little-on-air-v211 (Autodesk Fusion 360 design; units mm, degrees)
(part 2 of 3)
sketch "MODE terminal row clearance profile" plane through (0, 0, -13.9) normal (0, 0, 1) x axis (1, 0, 0)
  line L1 (63.1, 53.64) -> (56.9, 53.64)
  line L2 (63.1, 55.29) -> (63.1, 53.64)
  line L3 (56.9, 55.29) -> (63.1, 55.29)
  line L4 (56.9, 53.64) -> (56.9, 55.29)
  point P2 (56.9, 53.64)
  point P3 (63.1, 53.64)
  point P4 (63.1, 55.29)
  dimension "d508" distance P2 P3 = 6.2
  dimension "d509" distance P3 P4 = 1.65
extrude "Extrude67" cut sketch "MODE terminal row clearance profile" against normal blind 1.1
work_plane "WorkPlane68" AlongDistance -16.92 ExtraOffset 0
sketch "MODE terminal row clearance profile (1)" plane through (0, 0, -16.92) normal (0, 0, 1) x axis (1, 0, 0)
  line L1 (63.1, 53.64) -> (56.9, 53.64)
  line L2 (63.1, 55.29) -> (63.1, 53.64)
  line L3 (56.9, 55.29) -> (63.1, 55.29)
  line L4 (56.9, 53.64) -> (56.9, 55.29)
  point P2 (56.9, 53.64)
  point P3 (63.1, 53.64)
  point P4 (63.1, 55.29)
  dimension "d514" distance P2 P3 = 6.2
  dimension "d515" distance P3 P4 = 1.65
extrude "Extrude68" cut sketch "MODE terminal row clearance profile (1)" against normal blind 1.1
work_plane "WorkPlane69" AlongDistance -9.48 ExtraOffset 0
sketch "MODE direct actuator top aperture profile" plane through (0, 0, -9.48) normal (0, 0, 1) x axis (1, 0, 0)
  line L1 (62.2, 58.85) -> (57.8, 58.85)
  line L2 (62.2, 60.15) -> (62.2, 58.85)
  line L3 (57.8, 60.15) -> (62.2, 60.15)
  line L4 (57.8, 58.85) -> (57.8, 60.15)
  point P2 (57.8, 58.85)
  point P3 (62.2, 58.85)
  point P4 (62.2, 60.15)
  dimension "d520" distance P2 P3 = 4.4
  dimension "d521" distance P3 P4 = 1.3
extrude "Extrude69" cut sketch "MODE direct actuator top aperture profile" against normal blind 7.53
work_plane "WorkPlane70" AlongDistance -9.48 ExtraOffset 0
sketch "Side tongue clearance profile" plane through (0, 0, -9.48) normal (0, 0, 1) x axis (1, 0, 0)
  line L1 (4.1, 16.75) -> (2.4, 16.75)
  line L2 (4.1, 26.25) -> (4.1, 16.75)
  line L3 (2.4, 26.25) -> (4.1, 26.25)
  line L4 (2.4, 16.75) -> (2.4, 26.25)
  point P2 (2.4, 16.75)
  point P3 (4.1, 16.75)
  point P4 (4.1, 26.25)
  dimension "d526" distance P2 P3 = 1.7
  dimension "d527" distance P3 P4 = 9.5
work_plane "WorkPlane71" AlongDistance -9.48 ExtraOffset 0
sketch "Side tongue clearance profile (1)" plane through (0, 0, -9.48) normal (0, 0, 1) x axis (1, 0, 0)
  line L1 (117.6, 16.75) -> (115.9, 16.75)
  line L2 (117.6, 26.25) -> (117.6, 16.75)
  line L3 (115.9, 26.25) -> (117.6, 26.25)
  line L4 (115.9, 16.75) -> (115.9, 26.25)
  point P2 (115.9, 16.75)
  point P3 (117.6, 16.75)
  point P4 (117.6, 26.25)
  dimension "d532" distance P2 P3 = 1.7
  dimension "d533" distance P3 P4 = 9.5
work_plane "WorkPlane72" AlongDistance -9.48 ExtraOffset 0
sketch "Top tongue clearance profile" plane through (0, 0, -9.48) normal (0, 0, 1) x axis (1, 0, 0)
  line L1 (46.25, 55.9) -> (35.75, 55.9)
  line L2 (46.25, 57.6) -> (46.25, 55.9)
  line L3 (35.75, 57.6) -> (46.25, 57.6)
  line L4 (35.75, 55.9) -> (35.75, 57.6)
  point P2 (35.75, 55.9)
  point P3 (46.25, 55.9)
  point P4 (46.25, 57.6)
  dimension "d538" distance P2 P3 = 10.5
  dimension "d539" distance P3 P4 = 1.7
work_plane "WorkPlane73" AlongDistance -16.5 ExtraOffset 0
sketch "Charger rear LED viewing hole profile" plane through (0, 0, -16.5) normal (0, 0, 1) x axis (1, 0, 0)
  circle C1 centre (14, 49.4) radius 1.6
  dimension "d544" diameter C1 = 3.2
extrude "Extrude73" cut sketch "Charger rear LED viewing hole profile" against normal blind 7.7
work_plane "WorkPlane74" AlongDistance -16.5 ExtraOffset 0
sketch "Charger rear LED viewing hole profile (1)" plane through (0, 0, -16.5) normal (0, 0, 1) x axis (1, 0, 0)
  circle C1 centre (14, 44.65) radius 1.6
  dimension "d549" diameter C1 = 3.2
extrude "Extrude74" cut sketch "Charger rear LED viewing hole profile (1)" against normal blind 7.7
work_plane "WorkPlane75" AlongDistance -0.1 ExtraOffset 0
sketch "Angled pill vent" plane through (-0.1, 0, 0) normal (1, 0, 0) x axis (0, 0, -1)
  line L1 (17.3263, 17.9863) -> (17.1314, 17.8284)
  line L2 (17.5499, 18.1002) -> (17.3263, 17.9863)
  line L3 (17.7922, 18.1651) -> (17.5499, 18.1002)
  line L4 (18.0427, 18.1783) -> (17.7922, 18.1651)
  line L5 (18.2905, 18.139) -> (18.0427, 18.1783)
  line L6 (18.5247, 18.0491) -> (18.2905, 18.139)
  line L7 (18.7351, 17.9125) -> (18.5247, 18.0491)
  line L8 (18.9125, 17.7351) -> (18.7351, 17.9125)
  line L9 (19.0491, 17.5247) -> (18.9125, 17.7351)
  line L10 (19.139, 17.2905) -> (19.0491, 17.5247)
  line L11 (19.1783, 17.0427) -> (19.139, 17.2905)
  line L12 (19.1651, 16.7922) -> (19.1783, 17.0427)
  line L13 (19.1002, 16.5499) -> (19.1651, 16.7922)
  line L14 (18.9863, 16.3263) -> (19.1002, 16.5499)
  line L15 (18.8284, 16.1314) -> (18.9863, 16.3263)
  line L16 (14.8686, 12.1716) -> (18.8284, 16.1314)
  line L17 (14.6737, 12.0137) -> (14.8686, 12.1716)
  line L18 (14.4501, 11.8998) -> (14.6737, 12.0137)
  line L19 (14.2078, 11.8349) -> (14.4501, 11.8998)
  line L20 (13.9573, 11.8217) -> (14.2078, 11.8349)
  line L21 (13.7095, 11.861) -> (13.9573, 11.8217)
  line L22 (13.4753, 11.9509) -> (13.7095, 11.861)
  line L23 (13.2649, 12.0875) -> (13.4753, 11.9509)
  line L24 (13.0875, 12.2649) -> (13.2649, 12.0875)
  line L25 (12.9509, 12.4753) -> (13.0875, 12.2649)
  line L26 (12.861, 12.7095) -> (12.9509, 12.4753)
  line L27 (12.8217, 12.9573) -> (12.861, 12.7095)
  line L28 (12.8349, 13.2078) -> (12.8217, 12.9573)
  line L29 (12.8998, 13.4501) -> (12.8349, 13.2078)
  line L30 (13.0137, 13.6737) -> (12.8998, 13.4501)
  line L31 (13.1716, 13.8686) -> (13.0137, 13.6737)
  line L32 (17.1314, 17.8284) -> (13.1716, 13.8686)
extrude "Extrude75" cut sketch "Angled pill vent" along normal blind 2.65
work_plane "WorkPlane76" AlongDistance -0.1 ExtraOffset 0
sketch "Angled pill vent (1)" plane through (-0.1, 0, 0) normal (1, 0, 0) x axis (0, 0, -1)
  line L1 (17.3263, 26.9863) -> (17.1314, 26.8284)
  line L2 (17.5499, 27.1002) -> (17.3263, 26.9863)
  line L3 (17.7922, 27.1651) -> (17.5499, 27.1002)
  line L4 (18.0427, 27.1783) -> (17.7922, 27.1651)
  line L5 (18.2905, 27.139) -> (18.0427, 27.1783)
  line L6 (18.5247, 27.0491) -> (18.2905, 27.139)
  line L7 (18.7351, 26.9125) -> (18.5247, 27.0491)
  line L8 (18.9125, 26.7351) -> (18.7351, 26.9125)
  line L9 (19.0491, 26.5247) -> (18.9125, 26.7351)
  line L10 (19.139, 26.2905) -> (19.0491, 26.5247)
  line L11 (19.1783, 26.0427) -> (19.139, 26.2905)
  line L12 (19.1651, 25.7922) -> (19.1783, 26.0427)
  line L13 (19.1002, 25.5499) -> (19.1651, 25.7922)
  line L14 (18.9863, 25.3263) -> (19.1002, 25.5499)
  line L15 (18.8284, 25.1314) -> (18.9863, 25.3263)
  line L16 (14.8686, 21.1716) -> (18.8284, 25.1314)
  line L17 (14.6737, 21.0137) -> (14.8686, 21.1716)
  line L18 (14.4501, 20.8998) -> (14.6737, 21.0137)
  line L19 (14.2078, 20.8349) -> (14.4501, 20.8998)
  line L20 (13.9573, 20.8217) -> (14.2078, 20.8349)
  line L21 (13.7095, 20.861) -> (13.9573, 20.8217)
  line L22 (13.4753, 20.9509) -> (13.7095, 20.861)
  line L23 (13.2649, 21.0875) -> (13.4753, 20.9509)
  line L24 (13.0875, 21.2649) -> (13.2649, 21.0875)
  line L25 (12.9509, 21.4753) -> (13.0875, 21.2649)
  line L26 (12.861, 21.7095) -> (12.9509, 21.4753)
  line L27 (12.8217, 21.9573) -> (12.861, 21.7095)
  line L28 (12.8349, 22.2078) -> (12.8217, 21.9573)
  line L29 (12.8998, 22.4501) -> (12.8349, 22.2078)
  line L30 (13.0137, 22.6737) -> (12.8998, 22.4501)
  line L31 (13.1716, 22.8686) -> (13.0137, 22.6737)
  line L32 (17.1314, 26.8284) -> (13.1716, 22.8686)
extrude "Extrude76" cut sketch "Angled pill vent (1)" along normal blind 2.65
work_plane "WorkPlane77" AlongDistance -0.1 ExtraOffset 0
sketch "Angled pill vent (2)" plane through (-0.1, 0, 0) normal (1, 0, 0) x axis (0, 0, -1)
  line L1 (17.3263, 35.9863) -> (17.1314, 35.8284)
  line L2 (17.5499, 36.1002) -> (17.3263, 35.9863)
  line L3 (17.7922, 36.1651) -> (17.5499, 36.1002)
  line L4 (18.0427, 36.1783) -> (17.7922, 36.1651)
  line L5 (18.2905, 36.139) -> (18.0427, 36.1783)
  line L6 (18.5247, 36.0491) -> (18.2905, 36.139)
  line L7 (18.7351, 35.9125) -> (18.5247, 36.0491)
  line L8 (18.9125, 35.7351) -> (18.7351, 35.9125)
  line L9 (19.0491, 35.5247) -> (18.9125, 35.7351)
  line L10 (19.139, 35.2905) -> (19.0491, 35.5247)
  line L11 (19.1783, 35.0427) -> (19.139, 35.2905)
  line L12 (19.1651, 34.7922) -> (19.1783, 35.0427)
  line L13 (19.1002, 34.5499) -> (19.1651, 34.7922)
  line L14 (18.9863, 34.3263) -> (19.1002, 34.5499)
  line L15 (18.8284, 34.1314) -> (18.9863, 34.3263)
  line L16 (14.8686, 30.1716) -> (18.8284, 34.1314)
  line L17 (14.6737, 30.0137) -> (14.8686, 30.1716)
  line L18 (14.4501, 29.8998) -> (14.6737, 30.0137)
  line L19 (14.2078, 29.8349) -> (14.4501, 29.8998)
  line L20 (13.9573, 29.8217) -> (14.2078, 29.8349)
  line L21 (13.7095, 29.861) -> (13.9573, 29.8217)
  line L22 (13.4753, 29.9509) -> (13.7095, 29.861)
  line L23 (13.2649, 30.0875) -> (13.4753, 29.9509)
  line L24 (13.0875, 30.2649) -> (13.2649, 30.0875)
  line L25 (12.9509, 30.4753) -> (13.0875, 30.2649)
  line L26 (12.861, 30.7095) -> (12.9509, 30.4753)
  line L27 (12.8217, 30.9573) -> (12.861, 30.7095)
  line L28 (12.8349, 31.2078) -> (12.8217, 30.9573)
  line L29 (12.8998, 31.4501) -> (12.8349, 31.2078)
  line L30 (13.0137, 31.6737) -> (12.8998, 31.4501)
  line L31 (13.1716, 31.8686) -> (13.0137, 31.6737)
  line L32 (17.1314, 35.8284) -> (13.1716, 31.8686)
extrude "Extrude77" cut sketch "Angled pill vent (2)" along normal blind 2.65
work_plane "WorkPlane78" AlongDistance 117.5 ExtraOffset 0
sketch "Angled pill vent (3)" plane through (117.5, 0, 0) normal (1, 0, 0) x axis (0, 0, -1)
  line L1 (17.3263, 17.9863) -> (17.1314, 17.8284)
  line L2 (17.5499, 18.1002) -> (17.3263, 17.9863)
  line L3 (17.7922, 18.1651) -> (17.5499, 18.1002)
  line L4 (18.0427, 18.1783) -> (17.7922, 18.1651)
  line L5 (18.2905, 18.139) -> (18.0427, 18.1783)
  line L6 (18.5247, 18.0491) -> (18.2905, 18.139)
  line L7 (18.7351, 17.9125) -> (18.5247, 18.0491)
  line L8 (18.9125, 17.7351) -> (18.7351, 17.9125)
  line L9 (19.0491, 17.5247) -> (18.9125, 17.7351)
  line L10 (19.139, 17.2905) -> (19.0491, 17.5247)
  line L11 (19.1783, 17.0427) -> (19.139, 17.2905)
  line L12 (19.1651, 16.7922) -> (19.1783, 17.0427)
  line L13 (19.1002, 16.5499) -> (19.1651, 16.7922)
  line L14 (18.9863, 16.3263) -> (19.1002, 16.5499)
  line L15 (18.8284, 16.1314) -> (18.9863, 16.3263)
  line L16 (14.8686, 12.1716) -> (18.8284, 16.1314)
  line L17 (14.6737, 12.0137) -> (14.8686, 12.1716)
  line L18 (14.4501, 11.8998) -> (14.6737, 12.0137)
  line L19 (14.2078, 11.8349) -> (14.4501, 11.8998)
  line L20 (13.9573, 11.8217) -> (14.2078, 11.8349)
  line L21 (13.7095, 11.861) -> (13.9573, 11.8217)
  line L22 (13.4753, 11.9509) -> (13.7095, 11.861)
  line L23 (13.2649, 12.0875) -> (13.4753, 11.9509)
  line L24 (13.0875, 12.2649) -> (13.2649, 12.0875)
  line L25 (12.9509, 12.4753) -> (13.0875, 12.2649)
  line L26 (12.861, 12.7095) -> (12.9509, 12.4753)
  line L27 (12.8217, 12.9573) -> (12.861, 12.7095)
  line L28 (12.8349, 13.2078) -> (12.8217, 12.9573)
  line L29 (12.8998, 13.4501) -> (12.8349, 13.2078)
  line L30 (13.0137, 13.6737) -> (12.8998, 13.4501)
  line L31 (13.1716, 13.8686) -> (13.0137, 13.6737)
  line L32 (17.1314, 17.8284) -> (13.1716, 13.8686)
extrude "Extrude78" cut sketch "Angled pill vent (3)" along normal blind 2.65
work_plane "WorkPlane79" AlongDistance 117.5 ExtraOffset 0
sketch "Angled pill vent (4)" plane through (117.5, 0, 0) normal (1, 0, 0) x axis (0, 0, -1)
  line L1 (17.3263, 26.9863) -> (17.1314, 26.8284)
  line L2 (17.5499, 27.1002) -> (17.3263, 26.9863)
  line L3 (17.7922, 27.1651) -> (17.5499, 27.1002)
  line L4 (18.0427, 27.1783) -> (17.7922, 27.1651)
  line L5 (18.2905, 27.139) -> (18.0427, 27.1783)
  line L6 (18.5247, 27.0491) -> (18.2905, 27.139)
  line L7 (18.7351, 26.9125) -> (18.5247, 27.0491)
  line L8 (18.9125, 26.7351) -> (18.7351, 26.9125)
  line L9 (19.0491, 26.5247) -> (18.9125, 26.7351)
  line L10 (19.139, 26.2905) -> (19.0491, 26.5247)
  line L11 (19.1783, 26.0427) -> (19.139, 26.2905)
  line L12 (19.1651, 25.7922) -> (19.1783, 26.0427)
  line L13 (19.1002, 25.5499) -> (19.1651, 25.7922)
  line L14 (18.9863, 25.3263) -> (19.1002, 25.5499)
  line L15 (18.8284, 25.1314) -> (18.9863, 25.3263)
  line L16 (14.8686, 21.1716) -> (18.8284, 25.1314)
  line L17 (14.6737, 21.0137) -> (14.8686, 21.1716)
  line L18 (14.4501, 20.8998) -> (14.6737, 21.0137)
  line L19 (14.2078, 20.8349) -> (14.4501, 20.8998)
  line L20 (13.9573, 20.8217) -> (14.2078, 20.8349)
  line L21 (13.7095, 20.861) -> (13.9573, 20.8217)
  line L22 (13.4753, 20.9509) -> (13.7095, 20.861)
  line L23 (13.2649, 21.0875) -> (13.4753, 20.9509)
  line L24 (13.0875, 21.2649) -> (13.2649, 21.0875)
  line L25 (12.9509, 21.4753) -> (13.0875, 21.2649)
  line L26 (12.861, 21.7095) -> (12.9509, 21.4753)
  line L27 (12.8217, 21.9573) -> (12.861, 21.7095)
  line L28 (12.8349, 22.2078) -> (12.8217, 21.9573)
  line L29 (12.8998, 22.4501) -> (12.8349, 22.2078)
  line L30 (13.0137, 22.6737) -> (12.8998, 22.4501)
  line L31 (13.1716, 22.8686) -> (13.0137, 22.6737)
  line L32 (17.1314, 26.8284) -> (13.1716, 22.8686)
extrude "Extrude79" cut sketch "Angled pill vent (4)" along normal blind 2.65
work_plane "WorkPlane80" AlongDistance 117.5 ExtraOffset 0
sketch "Angled pill vent (5)" plane through (117.5, 0, 0) normal (1, 0, 0) x axis (0, 0, -1)
  line L1 (17.3263, 35.9863) -> (17.1314, 35.8284)
  line L2 (17.5499, 36.1002) -> (17.3263, 35.9863)
  line L3 (17.7922, 36.1651) -> (17.5499, 36.1002)
  line L4 (18.0427, 36.1783) -> (17.7922, 36.1651)
  line L5 (18.2905, 36.139) -> (18.0427, 36.1783)
  line L6 (18.5247, 36.0491) -> (18.2905, 36.139)
  line L7 (18.7351, 35.9125) -> (18.5247, 36.0491)
  line L8 (18.9125, 35.7351) -> (18.7351, 35.9125)
  line L9 (19.0491, 35.5247) -> (18.9125, 35.7351)
  line L10 (19.139, 35.2905) -> (19.0491, 35.5247)
  line L11 (19.1783, 35.0427) -> (19.139, 35.2905)
  line L12 (19.1651, 34.7922) -> (19.1783, 35.0427)
  line L13 (19.1002, 34.5499) -> (19.1651, 34.7922)
  line L14 (18.9863, 34.3263) -> (19.1002, 34.5499)
  line L15 (18.8284, 34.1314) -> (18.9863, 34.3263)
  line L16 (14.8686, 30.1716) -> (18.8284, 34.1314)
  line L17 (14.6737, 30.0137) -> (14.8686, 30.1716)
  line L18 (14.4501, 29.8998) -> (14.6737, 30.0137)
  line L19 (14.2078, 29.8349) -> (14.4501, 29.8998)
  line L20 (13.9573, 29.8217) -> (14.2078, 29.8349)
  line L21 (13.7095, 29.861) -> (13.9573, 29.8217)
  line L22 (13.4753, 29.9509) -> (13.7095, 29.861)
  line L23 (13.2649, 30.0875) -> (13.4753, 29.9509)
  line L24 (13.0875, 30.2649) -> (13.2649, 30.0875)
  line L25 (12.9509, 30.4753) -> (13.0875, 30.2649)
  line L26 (12.861, 30.7095) -> (12.9509, 30.4753)
  line L27 (12.8217, 30.9573) -> (12.861, 30.7095)
  line L28 (12.8349, 31.2078) -> (12.8217, 30.9573)
  line L29 (12.8998, 31.4501) -> (12.8349, 31.2078)
  line L30 (13.0137, 31.6737) -> (12.8998, 31.4501)
  line L31 (13.1716, 31.8686) -> (13.0137, 31.6737)
  line L32 (17.1314, 35.8284) -> (13.1716, 31.8686)
extrude "Extrude80" cut sketch "Angled pill vent (5)" along normal blind 2.65
work_plane "WorkPlane1" AlongDistance -9.65 ExtraOffset 0
sketch "Common 2.75 mm keeper rail profile" plane through (0, 0, -9.65) normal (0, 0, 1) x axis (1, 0, 0)
  line L1 (106.5, 34) -> (10.05, 34)
  line L2 (106.5, 38) -> (106.5, 34)
  line L3 (10.05, 38) -> (106.5, 38)
  line L4 (10.05, 34) -> (10.05, 38)
  point P2 (10.05, 34)
  point P3 (106.5, 34)
  point P4 (106.5, 38)
  dimension "d578" distance P2 P3 = 96.45
  dimension "d579" distance P3 P4 = 4
extrude "Extrude1" new body sketch "Common 2.75 mm keeper rail profile" against normal blind 2.75 bodies "Common 2.75 mm keeper rail"
work_plane "WorkPlane2" AlongDistance -9.65 ExtraOffset 0
sketch "Common screw seat profile" plane through (0, 0, -9.65) normal (0, 0, 1) x axis (1, 0, 0)
  line L1 (39.2, 33.8) -> (30.8, 33.8)
  line L2 (39.2, 42.2) -> (39.2, 33.8)
  line L3 (30.8, 42.2) -> (39.2, 42.2)
  line L4 (30.8, 33.8) -> (30.8, 42.2)
  point P2 (30.8, 33.8)
  point P3 (39.2, 33.8)
  point P4 (39.2, 42.2)
  dimension "d584" distance P2 P3 = 8.4
  dimension "d585" distance P3 P4 = 8.4
extrude "Extrude2" new body sketch "Common screw seat profile" against normal blind 2.75 bodies "Common screw seat"
work_plane "WorkPlane3" AlongDistance -9.65 ExtraOffset 0
sketch "Common screw seat profile (1)" plane through (0, 0, -9.65) normal (0, 0, 1) x axis (1, 0, 0)
  line L1 (77.2, 33.8) -> (68.8, 33.8)
  line L2 (77.2, 42.2) -> (77.2, 33.8)
  line L3 (68.8, 42.2) -> (77.2, 42.2)
  line L4 (68.8, 33.8) -> (68.8, 42.2)
  point P2 (68.8, 33.8)
  point P3 (77.2, 33.8)
  point P4 (77.2, 42.2)
  dimension "d590" distance P2 P3 = 8.4
  dimension "d591" distance P3 P4 = 8.4
extrude "Extrude3" new body sketch "Common screw seat profile (1)" against normal blind 2.75 bodies "Common screw seat (1)"
work_plane "WorkPlane4" AlongDistance -9.65 ExtraOffset 0
sketch "Charger side keeper rail profile" plane through (0, 0, -9.65) normal (0, 0, 1) x axis (1, 0, 0)
  line L1 (14.5, 33.8) -> (10.05, 33.8)
  line L2 (14.5, 57.35) -> (14.5, 33.8)
  line L3 (10.05, 57.35) -> (14.5, 57.35)
  line L4 (10.05, 33.8) -> (10.05, 57.35)
  point P2 (10.05, 33.8)
  point P3 (14.5, 33.8)
  point P4 (14.5, 57.35)
  dimension "d596" distance P2 P3 = 4.45
  dimension "d597" distance P3 P4 = 23.55
extrude "Extrude4" new body sketch "Charger side keeper rail profile" against normal blind 2.75 bodies "Charger side keeper rail"
work_plane "WorkPlane5" AlongDistance -9.65 ExtraOffset 0
sketch "Charger side keeper rail profile (1)" plane through (0, 0, -9.65) normal (0, 0, 1) x axis (1, 0, 0)
  line L1 (31.95, 33.8) -> (27.5, 33.8)
  line L2 (31.95, 57.35) -> (31.95, 33.8)
  line L3 (27.5, 57.35) -> (31.95, 57.35)
  line L4 (27.5, 33.8) -> (27.5, 57.35)
  point P2 (27.5, 33.8)
  point P3 (31.95, 33.8)
  point P4 (31.95, 57.35)
  dimension "d602" distance P2 P3 = 4.45
  dimension "d603" distance P3 P4 = 23.55
extrude "Extrude5" new body sketch "Charger side keeper rail profile (1)" against normal blind 2.75 bodies "Charger side keeper rail (1)"
work_plane "WorkPlane6" AlongDistance -12.35 ExtraOffset 0
sketch "Charger short keeper pad profile" plane through (0, 0, -12.35) normal (0, 0, 1) x axis (1, 0, 0)
  line L1 (14.65, 34.3) -> (12.25, 34.3)
  line L2 (14.65, 36.3) -> (14.65, 34.3)
  line L3 (12.25, 36.3) -> (14.65, 36.3)
  line L4 (12.25, 34.3) -> (12.25, 36.3)
  point P2 (12.25, 34.3)
  point P3 (14.65, 34.3)
  point P4 (14.65, 36.3)
  dimension "d608" distance P2 P3 = 2.4
  dimension "d609" distance P3 P4 = 2
extrude "Extrude6" new body sketch "Charger short keeper pad profile" against normal blind 2.8 bodies "Charger short keeper pad"
work_plane "WorkPlane7" AlongDistance -12.35 ExtraOffset 0
sketch "Charger short keeper pad profile (1)" plane through (0, 0, -12.35) normal (0, 0, 1) x axis (1, 0, 0)
  line L1 (14.65, 53.5) -> (12.25, 53.5)
  line L2 (14.65, 56.5) -> (14.65, 53.5)
  line L3 (12.25, 56.5) -> (14.65, 56.5)
  line L4 (12.25, 53.5) -> (12.25, 56.5)
  point P2 (12.25, 53.5)
  point P3 (14.65, 53.5)
  point P4 (14.65, 56.5)
  dimension "d614" distance P2 P3 = 2.4
  dimension "d615" distance P3 P4 = 3
extrude "Extrude7" new body sketch "Charger short keeper pad profile (1)" against normal blind 2.8 bodies "Charger short keeper pad (1)"
work_plane "WorkPlane8" AlongDistance -12.35 ExtraOffset 0
sketch "Charger short keeper pad profile (2)" plane through (0, 0, -12.35) normal (0, 0, 1) x axis (1, 0, 0)
  line L1 (29.75, 34.3) -> (27.35, 34.3)
  line L2 (29.75, 36.3) -> (29.75, 34.3)
  line L3 (27.35, 36.3) -> (29.75, 36.3)
  line L4 (27.35, 34.3) -> (27.35, 36.3)
  point P2 (27.35, 34.3)
  point P3 (29.75, 34.3)
  point P4 (29.75, 36.3)
  dimension "d620" distance P2 P3 = 2.4
  dimension "d621" distance P3 P4 = 2
extrude "Extrude8" new body sketch "Charger short keeper pad profile (2)" against normal blind 2.8 bodies "Charger short keeper pad (2)"
work_plane "WorkPlane9" AlongDistance -12.35 ExtraOffset 0
sketch "Charger short keeper pad profile (3)" plane through (0, 0, -12.35) normal (0, 0, 1) x axis (1, 0, 0)
  line L1 (29.75, 53.5) -> (27.35, 53.5)
  line L2 (29.75, 56.5) -> (29.75, 53.5)
  line L3 (27.35, 56.5) -> (29.75, 56.5)
  line L4 (27.35, 53.5) -> (27.35, 56.5)
  point P2 (27.35, 53.5)
  point P3 (29.75, 53.5)
  point P4 (29.75, 56.5)
  dimension "d626" distance P2 P3 = 2.4
  dimension "d627" distance P3 P4 = 3
extrude "Extrude9" new body sketch "Charger short keeper pad profile (3)" against normal blind 2.8 bodies "Charger short keeper pad (3)"
work_plane "WorkPlane10" AlongDistance -9.65 ExtraOffset 0
sketch "Charger roof crossbar profile" plane through (0, 0, -9.65) normal (0, 0, 1) x axis (1, 0, 0)
  line L1 (31.95, 54.65) -> (10.05, 54.65)
  line L2 (31.95, 57.35) -> (31.95, 54.65)
  line L3 (10.05, 57.35) -> (31.95, 57.35)
  line L4 (10.05, 54.65) -> (10.05, 57.35)
  point P2 (10.05, 54.65)
  point P3 (31.95, 54.65)
  point P4 (31.95, 57.35)
  dimension "d632" distance P2 P3 = 21.9
  dimension "d633" distance P3 P4 = 2.7
extrude "Extrude10" new body sketch "Charger roof crossbar profile" against normal blind 2.75 bodies "Charger roof crossbar"
work_plane "WorkPlane11" AlongDistance -9.65 ExtraOffset 0
sketch "Charger square USB roof profile" plane through (0, 0, -9.65) normal (0, 0, 1) x axis (1, 0, 0)
  line L1 (25.225, 57.3) -> (15.775, 57.3)
  line L2 (25.225, 59.75) -> (25.225, 57.3)
  line L3 (15.775, 59.75) -> (25.225, 59.75)
  line L4 (15.775, 57.3) -> (15.775, 59.75)
  point P2 (15.775, 57.3)
  point P3 (25.225, 57.3)
  point P4 (25.225, 59.75)
  dimension "d638" distance P2 P3 = 9.45
  dimension "d639" distance P3 P4 = 2.45
extrude "Extrude11" new body sketch "Charger square USB roof profile" against normal blind 6.35 bodies "Charger square USB roof"
work_plane "WorkPlane12" AlongDistance -9.65 ExtraOffset 0
sketch "POWER broad side arm profile" plane through (0, 0, -9.65) normal (0, 0, 1) x axis (1, 0, 0)
  line L1 (36.2, 36) -> (33, 36)
  line L2 (36.2, 57.5) -> (36.2, 36)
  line L3 (33, 57.5) -> (36.2, 57.5)
  line L4 (33, 36) -> (33, 57.5)
  point P2 (33, 36)
  point P3 (36.2, 36)
  point P4 (36.2, 57.5)
  dimension "d644" distance P2 P3 = 3.2
  dimension "d645" distance P3 P4 = 21.5
extrude "Extrude12" new body sketch "POWER broad side arm profile" against normal blind 2.75 bodies "POWER broad side arm"
work_plane "WorkPlane13" AlongDistance -9.65 ExtraOffset 0
sketch "POWER broad side arm profile (1)" plane through (0, 0, -9.65) normal (0, 0, 1) x axis (1, 0, 0)
  line L1 (50.4, 36) -> (47.2, 36)
  line L2 (50.4, 57.5) -> (50.4, 36)
  line L3 (47.2, 57.5) -> (50.4, 57.5)
  line L4 (47.2, 36) -> (47.2, 57.5)
  point P2 (47.2, 36)
  point P3 (50.4, 36)
  point P4 (50.4, 57.5)
  dimension "d650" distance P2 P3 = 3.2
  dimension "d651" distance P3 P4 = 21.5
extrude "Extrude13" new body sketch "POWER broad side arm profile (1)" against normal blind 2.75 bodies "POWER broad side arm (1)"
work_plane "WorkPlane14" AlongDistance -9.65 ExtraOffset 0
sketch "POWER upper crossbar profile" plane through (0, 0, -9.65) normal (0, 0, 1) x axis (1, 0, 0)
  line L1 (50.4, 54.5) -> (33, 54.5)
  line L2 (50.4, 57.3) -> (50.4, 54.5)
  line L3 (33, 57.3) -> (50.4, 57.3)
  line L4 (33, 54.5) -> (33, 57.3)
  point P2 (33, 54.5)
  point P3 (50.4, 54.5)
  point P4 (50.4, 57.3)
  dimension "d656" distance P2 P3 = 17.4
  dimension "d657" distance P3 P4 = 2.8
extrude "Extrude14" new body sketch "POWER upper crossbar profile" against normal blind 2.75 bodies "POWER upper crossbar"
work_plane "WorkPlane15" AlongDistance -12.35 ExtraOffset 0
sketch "POWER short keeper pad profile" plane through (0, 0, -12.35) normal (0, 0, 1) x axis (1, 0, 0)
  line L1 (39, 54) -> (36.6, 54)
  line L2 (39, 56.5) -> (39, 54)
  line L3 (36.6, 56.5) -> (39, 56.5)
  line L4 (36.6, 54) -> (36.6, 56.5)
  point P2 (36.6, 54)
  point P3 (39, 54)
  point P4 (39, 56.5)
  dimension "d662" distance P2 P3 = 2.4
  dimension "d663" distance P3 P4 = 2.5
extrude "Extrude15" new body sketch "POWER short keeper pad profile" against normal blind 1.45 bodies "POWER short keeper pad"
work_plane "WorkPlane16" AlongDistance -12.35 ExtraOffset 0
sketch "POWER short keeper pad profile (1)" plane through (0, 0, -12.35) normal (0, 0, 1) x axis (1, 0, 0)
  line L1 (45.4, 54) -> (43, 54)
  line L2 (45.4, 56.5) -> (45.4, 54)
  line L3 (43, 56.5) -> (45.4, 56.5)
  line L4 (43, 54) -> (43, 56.5)
  point P2 (43, 54)
  point P3 (45.4, 54)
  point P4 (45.4, 56.5)
  dimension "d668" distance P2 P3 = 2.4
  dimension "d669" distance P3 P4 = 2.5
extrude "Extrude16" new body sketch "POWER short keeper pad profile (1)" against normal blind 1.45 bodies "POWER short keeper pad (1)"
work_plane "WorkPlane17" AlongDistance -9.65 ExtraOffset 0
sketch "POWER square lever roof profile" plane through (0, 0, -9.65) normal (0, 0, 1) x axis (1, 0, 0)
  line L1 (44.15, 57.25) -> (37.85, 57.25)
  line L2 (44.15, 59.75) -> (44.15, 57.25)
  line L3 (37.85, 59.75) -> (44.15, 59.75)
  line L4 (37.85, 57.25) -> (37.85, 59.75)
  point P2 (37.85, 57.25)
  point P3 (44.15, 57.25)
  point P4 (44.15, 59.75)
  dimension "d674" distance P2 P3 = 6.3
  dimension "d675" distance P3 P4 = 2.5
extrude "Extrude17" new body sketch "POWER square lever roof profile" against normal blind 5.575 bodies "POWER square lever roof"
work_plane "WorkPlane18" AlongDistance -9.65 ExtraOffset 0
sketch "MODE broad side arm profile" plane through (0, 0, -9.65) normal (0, 0, 1) x axis (1, 0, 0)
  line L1 (56.6, 36) -> (53.1, 36)
  line L2 (56.6, 57.5) -> (56.6, 36)
  line L3 (53.1, 57.5) -> (56.6, 57.5)
  line L4 (53.1, 36) -> (53.1, 57.5)
  point P2 (53.1, 36)
  point P3 (56.6, 36)
  point P4 (56.6, 57.5)
  dimension "d680" distance P2 P3 = 3.5
  dimension "d681" distance P3 P4 = 21.5
extrude "Extrude18" new body sketch "MODE broad side arm profile" against normal blind 2.75 bodies "MODE broad side arm"
work_plane "WorkPlane19" AlongDistance -9.65 ExtraOffset 0
sketch "MODE broad side arm profile (1)" plane through (0, 0, -9.65) normal (0, 0, 1) x axis (1, 0, 0)
  line L1 (66.7, 36) -> (63.2, 36)
  line L2 (66.7, 57.5) -> (66.7, 36)
  line L3 (63.2, 57.5) -> (66.7, 57.5)
  line L4 (63.2, 36) -> (63.2, 57.5)
  point P2 (63.2, 36)
  point P3 (66.7, 36)
  point P4 (66.7, 57.5)
  dimension "d686" distance P2 P3 = 3.5
  dimension "d687" distance P3 P4 = 21.5
extrude "Extrude19" new body sketch "MODE broad side arm profile (1)" against normal blind 2.75 bodies "MODE broad side arm (1)"
work_plane "WorkPlane20" AlongDistance -9.65 ExtraOffset 0
sketch "MODE upper crossbar profile" plane through (0, 0, -9.65) normal (0, 0, 1) x axis (1, 0, 0)
  line L1 (66.7, 54.65) -> (53.1, 54.65)
  line L2 (66.7, 57.35) -> (66.7, 54.65)
  line L3 (53.1, 57.35) -> (66.7, 57.35)
  line L4 (53.1, 54.65) -> (53.1, 57.35)
  point P2 (53.1, 54.65)
  point P3 (66.7, 54.65)
  point P4 (66.7, 57.35)
  dimension "d692" distance P2 P3 = 13.6
  dimension "d693" distance P3 P4 = 2.7
extrude "Extrude20" new body sketch "MODE upper crossbar profile" against normal blind 2.75 bodies "MODE upper crossbar"
work_plane "WorkPlane21" AlongDistance -12.35 ExtraOffset 0
sketch "MODE keeper 0.15 body freeplay profile" plane through (0, 0, -12.35) normal (0, 0, 1) x axis (1, 0, 0)
  line L1 (57.95, 55.85) -> (55.45, 55.85)
  line L2 (57.95, 57.75) -> (57.95, 55.85)
  line L3 (55.45, 57.75) -> (57.95, 57.75)
  line L4 (55.45, 55.85) -> (55.45, 57.75)
  point P2 (55.45, 55.85)
  point P3 (57.95, 55.85)
  point P4 (57.95, 57.75)
  dimension "d698" distance P2 P3 = 2.5
  dimension "d699" distance P3 P4 = 1.9
extrude "Extrude21" new body sketch "MODE keeper 0.15 body freeplay profile" against normal blind 1.6 bodies "MODE keeper 0.15 body freeplay"
work_plane "WorkPlane22" AlongDistance -12.35 ExtraOffset 0
sketch "MODE keeper 0.15 body freeplay profile (1)" plane through (0, 0, -12.35) normal (0, 0, 1) x axis (1, 0, 0)
  line L1 (64.55, 55.85) -> (62.05, 55.85)
  line L2 (64.55, 57.75) -> (64.55, 55.85)
  line L3 (62.05, 57.75) -> (64.55, 57.75)
  line L4 (62.05, 55.85) -> (62.05, 57.75)
  point P2 (62.05, 55.85)
  point P3 (64.55, 55.85)
  point P4 (64.55, 57.75)
  dimension "d704" distance P2 P3 = 2.5
  dimension "d705" distance P3 P4 = 1.9
extrude "Extrude22" new body sketch "MODE keeper 0.15 body freeplay profile (1)" against normal blind 1.6 bodies "MODE keeper 0.15 body freeplay (1)"
work_plane "WorkPlane23" AlongDistance -9.65 ExtraOffset 0
sketch "MODE square actuator roof profile" plane through (0, 0, -9.65) normal (0, 0, 1) x axis (1, 0, 0)
  line L1 (62.2, 57.25) -> (57.8, 57.25)
  line L2 (62.2, 59.75) -> (62.2, 57.25)
  line L3 (57.8, 59.75) -> (62.2, 59.75)
  line L4 (57.8, 57.25) -> (57.8, 59.75)
  point P2 (57.8, 57.25)
  point P3 (62.2, 57.25)
  point P4 (62.2, 59.75)
  dimension "d710" distance P2 P3 = 4.4
  dimension "d711" distance P3 P4 = 2.5
extrude "Extrude23" new body sketch "MODE square actuator roof profile" against normal blind 5.06 bodies "MODE square actuator roof"
work_plane "WorkPlane24" AlongDistance -9.65 ExtraOffset 0
sketch "XIAO broad side rail profile" plane through (0, 0, -9.65) normal (0, 0, 1) x axis (1, 0, 0)
  line L1 (90, 35.8) -> (86.5, 35.8)
  line L2 (90, 57.8) -> (90, 35.8)
  line L3 (86.5, 57.8) -> (90, 57.8)
  line L4 (86.5, 35.8) -> (86.5, 57.8)
  point P2 (86.5, 35.8)
  point P3 (90, 35.8)
  point P4 (90, 57.8)
  dimension "d716" distance P2 P3 = 3.5
  dimension "d717" distance P3 P4 = 22
extrude "Extrude24" new body sketch "XIAO broad side rail profile" against normal blind 2.75 bodies "XIAO broad side rail"
work_plane "WorkPlane25" AlongDistance -9.65 ExtraOffset 0
sketch "XIAO broad side rail profile (1)" plane through (0, 0, -9.65) normal (0, 0, 1) x axis (1, 0, 0)
  line L1 (109.5, 35.8) -> (106, 35.8)
  line L2 (109.5, 57.8) -> (109.5, 35.8)
  line L3 (106, 57.8) -> (109.5, 57.8)
  line L4 (106, 35.8) -> (106, 57.8)
  point P2 (106, 35.8)
  point P3 (109.5, 35.8)
  point P4 (109.5, 57.8)
  dimension "d722" distance P2 P3 = 3.5
  dimension "d723" distance P3 P4 = 22
extrude "Extrude25" new body sketch "XIAO broad side rail profile (1)" against normal blind 2.75 bodies "XIAO broad side rail (1)"
work_plane "WorkPlane26" AlongDistance -9.65 ExtraOffset 0
sketch "XIAO upper crossbar profile" plane through (0, 0, -9.65) normal (0, 0, 1) x axis (1, 0, 0)
  line L1 (109.5, 54.4) -> (86.5, 54.4)
  line L2 (109.5, 57.8) -> (109.5, 54.4)
  line L3 (86.5, 57.8) -> (109.5, 57.8)
  line L4 (86.5, 54.4) -> (86.5, 57.8)
  point P2 (86.5, 54.4)
  point P3 (109.5, 54.4)
  point P4 (109.5, 57.8)
  dimension "d728" distance P2 P3 = 23
  dimension "d729" distance P3 P4 = 3.4
extrude "Extrude26" new body sketch "XIAO upper crossbar profile" against normal blind 2.75 bodies "XIAO upper crossbar"
work_plane "WorkPlane27" AlongDistance -12.35 ExtraOffset 0
sketch "XIAO short end keeper pad profile" plane through (0, 0, -12.35) normal (0, 0, 1) x axis (1, 0, 0)
  line L1 (91.25, 36.8) -> (89.25, 36.8)
  line L2 (91.25, 38.2) -> (91.25, 36.8)
  line L3 (89.25, 38.2) -> (91.25, 38.2)
  line L4 (89.25, 36.8) -> (89.25, 38.2)
  point P2 (89.25, 36.8)
  point P3 (91.25, 36.8)
  point P4 (91.25, 38.2)
  dimension "d734" distance P2 P3 = 2
  dimension "d735" distance P3 P4 = 1.4
extrude "Extrude27" new body sketch "XIAO short end keeper pad profile" against normal blind 6 bodies "XIAO short end keeper pad"
work_plane "WorkPlane28" AlongDistance -12.35 ExtraOffset 0
sketch "XIAO short end keeper pad profile (1)" plane through (0, 0, -12.35) normal (0, 0, 1) x axis (1, 0, 0)
  line L1 (91.25, 56.65) -> (89.25, 56.65)
  line L2 (91.25, 57.8) -> (91.25, 56.65)
  line L3 (89.25, 57.8) -> (91.25, 57.8)
  line L4 (89.25, 56.65) -> (89.25, 57.8)
  point P2 (89.25, 56.65)
  point P3 (91.25, 56.65)
  point P4 (91.25, 57.8)
  dimension "d740" distance P2 P3 = 2
  dimension "d741" distance P3 P4 = 1.15
extrude "Extrude28" new body sketch "XIAO short end keeper pad profile (1)" against normal blind 6 bodies "XIAO short end keeper pad (1)"
work_plane "WorkPlane29" AlongDistance -12.35 ExtraOffset 0
sketch "XIAO short end keeper pad profile (2)" plane through (0, 0, -12.35) normal (0, 0, 1) x axis (1, 0, 0)
  line L1 (106.55, 36.8) -> (104.55, 36.8)
  line L2 (106.55, 38.2) -> (106.55, 36.8)
  line L3 (104.55, 38.2) -> (106.55, 38.2)
  line L4 (104.55, 36.8) -> (104.55, 38.2)
  point P2 (104.55, 36.8)
  point P3 (106.55, 36.8)
  point P4 (106.55, 38.2)
  dimension "d746" distance P2 P3 = 2
  dimension "d747" distance P3 P4 = 1.4
extrude "Extrude29" new body sketch "XIAO short end keeper pad profile (2)" against normal blind 6 bodies "XIAO short end keeper pad (2)"
work_plane "WorkPlane30" AlongDistance -12.35 ExtraOffset 0
sketch "XIAO short end keeper pad profile (3)" plane through (0, 0, -12.35) normal (0, 0, 1) x axis (1, 0, 0)
  line L1 (106.55, 56.65) -> (104.55, 56.65)
  line L2 (106.55, 57.8) -> (106.55, 56.65)
  line L3 (104.55, 57.8) -> (106.55, 57.8)
  line L4 (104.55, 56.65) -> (104.55, 57.8)
  point P2 (104.55, 56.65)
  point P3 (106.55, 56.65)
  point P4 (106.55, 57.8)
  dimension "d752" distance P2 P3 = 2
  dimension "d753" distance P3 P4 = 1.15
extrude "Extrude30" new body sketch "XIAO short end keeper pad profile (3)" against normal blind 6 bodies "XIAO short end keeper pad (3)"
work_plane "WorkPlane31" AlongDistance -9.65 ExtraOffset 0
sketch "XIAO square USB roof profile" plane through (0, 0, -9.65) normal (0, 0, 1) x axis (1, 0, 0)
  line L1 (102.685, 57.3) -> (93.115, 57.3)
  line L2 (102.685, 59.75) -> (102.685, 57.3)
  line L3 (93.115, 59.75) -> (102.685, 59.75)
  line L4 (93.115, 57.3) -> (93.115, 59.75)
  point P2 (93.115, 57.3)
  point P3 (102.685, 57.3)
  point P4 (102.685, 59.75)
  dimension "d758" distance P2 P3 = 9.57
  dimension "d759" distance P3 P4 = 2.45
extrude "Extrude31" new body sketch "XIAO square USB roof profile" against normal blind 5.38 bodies "XIAO square USB roof"
work_plane "WorkPlane32" AlongDistance -12.35 ExtraOffset 0
sketch "Deep keyed reset guide profile" plane through (0, 0, -12.35) normal (0, 0, 1) x axis (1, 0, 0)
  line L1 (95.515, 52.6) -> (88.515, 52.6)
  line L2 (95.515, 59.4) -> (95.515, 52.6)
  line L3 (88.515, 59.4) -> (95.515, 59.4)
  line L4 (88.515, 52.6) -> (88.515, 59.4)
  point P2 (88.515, 52.6)
  point P3 (95.515, 52.6)
  point P4 (95.515, 59.4)
  dimension "d764" distance P2 P3 = 7
  dimension "d765" distance P3 P4 = 6.8
extrude "Extrude32" new body sketch "Deep keyed reset guide profile" against normal blind 2.65 bodies "Deep keyed reset guide"
combine "Combine1" bodies "Common screw seat", "Common screw seat (1)", "Charger side keeper rail", "Charger side keeper rail (1)", "Charger short keeper pad", "Charger short keeper pad (1)", "Charger short keeper pad (2)", "Charger short keeper pad (3)"
work_plane "WorkPlane33" AlongDistance -9.63 ExtraOffset 0
sketch "M3 keeper clearance profile" plane through (0, 0, -9.63) normal (0, 0, 1) x axis (1, 0, 0)
  circle C1 centre (35, 38) radius 1.8
  dimension "d770" diameter C1 = 3.6
extrude "Extrude33" cut sketch "M3 keeper clearance profile" against normal blind 2.79
work_plane "WorkPlane34" AlongDistance -9.63 ExtraOffset 0
sketch "M3 keeper clearance profile (1)" plane through (0, 0, -9.63) normal (0, 0, 1) x axis (1, 0, 0)
  circle C1 centre (73, 38) radius 1.8
  dimension "d775" diameter C1 = 3.6
extrude "Extrude34" cut sketch "M3 keeper clearance profile (1)" against normal blind 2.79
work_plane "WorkPlane35" AlongDistance -9.63 ExtraOffset 0
sketch "Rear reset running guide profile" plane through (0, 0, -9.63) normal (0, 0, 1) x axis (1, 0, 0)
  line L1 (93.415, 54.4) -> (90.615, 54.4)
  line L2 (93.415, 57.6) -> (93.415, 54.4)
  line L3 (90.615, 57.6) -> (93.415, 57.6)
  line L4 (90.615, 54.4) -> (90.615, 57.6)
  point P2 (90.615, 54.4)
  point P3 (93.415, 54.4)
  point P4 (93.415, 57.6)
  dimension "d780" distance P2 P3 = 2.8
  dimension "d781" distance P3 P4 = 3.2
extrude "Extrude35" cut sketch "Rear reset running guide profile" against normal blind 5.4
work_plane "WorkPlane36" AlongDistance -9.63 ExtraOffset 0
sketch "RGB6 unobstructed front sight profile" plane through (0, 0, -9.63) normal (0, 0, 1) x axis (1, 0, 0)
  circle C1 centre (103.605, 55.006) radius 1.6
  dimension "d786" diameter C1 = 3.2
extrude "Extrude36" cut sketch "RGB6 unobstructed front sight profile" against normal blind 9
work_plane "WorkPlane37" AlongDistance -9.48 ExtraOffset 0
sketch "Top front tongue clearance profile" plane through (0, 0, -9.48) normal (0, 0, 1) x axis (1, 0, 0)
  line L1 (46.25, 55.9) -> (35.75, 55.9)
  line L2 (46.25, 57.6) -> (46.25, 55.9)
  line L3 (35.75, 57.6) -> (46.25, 57.6)
  line L4 (35.75, 55.9) -> (35.75, 57.6)
  point P2 (35.75, 55.9)
  point P3 (46.25, 55.9)
  point P4 (46.25, 57.6)
  dimension "d791" distance P2 P3 = 10.5
  dimension "d792" distance P3 P4 = 1.7
extrude "Extrude37" cut sketch "Top front tongue clearance profile" against normal blind 1.77
work_plane "WorkPlane1" AlongDistance 2.5 ExtraOffset 0
sketch "Rounded front finger and keyed shaft profile" plane through (0, 0, 2.5) normal (0, 0, 1) x axis (1, 0, 0)
  line L1 (92.765, 54.6) -> (91.265, 54.6)
  line L2 (93.215, 56.95) -> (93.215, 55.05)
  line L3 (91.265, 57.4) -> (92.765, 57.4)
  line L4 (90.815, 55.05) -> (90.815, 56.95)
  arc A1 centre (92.765, 55.05) radius 0.45 clockwise from (93.215, 55.05) to (92.765, 54.6)
  arc A2 centre (92.765, 56.95) radius 0.45 clockwise from (92.765, 57.4) to (93.215, 56.95)
  arc A3 centre (91.265, 56.95) radius 0.45 clockwise from (90.815, 56.95) to (91.265, 57.4)
  arc A4 centre (91.265, 55.05) radius 0.45 clockwise from (91.265, 54.6) to (90.815, 55.05)
extrude "Extrude1" new body sketch "Rounded front finger and keyed shaft profile" against normal blind 17.3 bodies "Rounded front finger and keyed shaft"
work_plane "WorkPlane2" AlongDistance -6 ExtraOffset 0
sketch "Broad internal captive flange profile" plane through (0, 0, -6) normal (0, 0, 1) x axis (1, 0, 0)
  line L1 (94.015, 53.4) -> (90.015, 53.4)
  line L2 (94.615, 58) -> (94.615, 54)
  line L3 (90.015, 58.6) -> (94.015, 58.6)
  line L4 (89.415, 54) -> (89.415, 58)
  arc A1 centre (94.015, 54) radius 0.6 clockwise from (94.615, 54) to (94.015, 53.4)
  arc A2 centre (94.015, 58) radius 0.6 clockwise from (94.015, 58.6) to (94.615, 58)
  arc A3 centre (90.015, 58) radius 0.6 clockwise from (89.415, 58) to (90.015, 58.6)
  arc A4 centre (90.015, 54) radius 0.6 clockwise from (90.015, 53.4) to (89.415, 54)
extrude "Extrude2" new body sketch "Broad internal captive flange profile" against normal blind 2.85 bodies "Broad internal captive flange"
work_plane "WorkPlane3" AlongDistance -14.7 ExtraOffset 0
sketch "Narrow USB-clear reset contact profile" plane through (0, 0, -14.7) normal (0, 0, 1) x axis (1, 0, 0)
  line L1 (93.015, 55) -> (91.015, 55)
  line L2 (93.015, 57) -> (93.015, 55)
  line L3 (91.015, 57) -> (93.015, 57)
  line L4 (91.015, 55) -> (91.015, 57)
  point P2 (91.015, 55)
  point P3 (93.015, 55)
  point P4 (93.015, 57)
  dimension "d805" distance P2 P3 = 2
  dimension "d806" distance P3 P4 = 2
extrude "Extrude3" new body sketch "Narrow USB-clear reset contact profile" against normal blind 2.95 bodies "Narrow USB-clear reset contact"
combine "Combine1" bodies "Broad internal captive flange", "Narrow USB-clear reset contact"
work_plane "WorkPlane1" AlongDistance -10.9 ExtraOffset 0
sketch "Battery pouch profile" plane through (0, 0, -10.9) normal (0, 0, 1) x axis (1, 0, 0)
  line L1 (87, 11) -> (35, 11)
  line L2 (87, 32) -> (87, 11)
  line L3 (35, 32) -> (87, 32)
  line L4 (35, 11) -> (35, 32)
  point P2 (35, 11)
  point P3 (87, 11)
  point P4 (87, 32)
  dimension "d811" distance P2 P3 = 52
  dimension "d812" distance P3 P4 = 21
extrude "Extrude1" new body sketch "Battery pouch profile" against normal blind 10 bodies "Battery pouch"
work_plane "WorkPlane1" AlongDistance 15 ExtraOffset 0
sketch "Sketch1" plane through (0, 15, 0) normal (0, 1, 0) x axis (1, 0, 0)
  circle C1 centre (103, 16) radius 4
extrude "Extrude1" new body sketch "Sketch1" along normal blind 11.5 bodies "C1 inline capacitor"
work_plane "WorkPlane81" AlongDistance -9.48 ExtraOffset 0
sketch "Charger upper PCB loading recess profile" plane through (0, 0, -9.48) normal (0, 0, 1) x axis (1, 0, 0)
  line L1 (30.05, 57.35) -> (11.95, 57.35)
  line L2 (30.05, 58.65) -> (30.05, 57.35)
  line L3 (11.95, 58.65) -> (30.05, 58.65)
  line L4 (11.95, 57.35) -> (11.95, 58.65)
  point P2 (11.95, 57.35)
  point P3 (30.05, 57.35)
  point P4 (30.05, 58.65)
  dimension "d821" distance P2 P3 = 18.1
  dimension "d822" distance P3 P4 = 1.3
extrude "Extrude81" cut sketch "Charger upper PCB loading recess profile" against normal blind 7.12
work_plane "WorkPlane82" AlongDistance -9.48 ExtraOffset 0
sketch "XIAO upper PCB loading recess profile" plane through (0, 0, -9.48) normal (0, 0, 1) x axis (1, 0, 0)
  line L1 (107.05, 57.35) -> (88.75, 57.35)
  line L2 (107.05, 58.05) -> (107.05, 57.35)
  line L3 (88.75, 58.05) -> (107.05, 58.05)
  line L4 (88.75, 57.35) -> (88.75, 58.05)
  point P2 (88.75, 57.35)
  point P3 (107.05, 57.35)
  point P4 (107.05, 58.05)
  dimension "d827" distance P2 P3 = 18.3
  dimension "d828" distance P3 P4 = 0.7
extrude "Extrude82" cut sketch "XIAO upper PCB loading recess profile" against normal blind 10.47
work_plane "WorkPlane38" AlongDistance -15.05 ExtraOffset 0
sketch "Charger roof clears PCB underside profile" plane through (0, 0, -15.05) normal (0, 0, 1) x axis (1, 0, 0)
  line L1 (30.05, 57.3) -> (11.95, 57.3)
  line L2 (30.05, 58.65) -> (30.05, 57.3)
  line L3 (11.95, 58.65) -> (30.05, 58.65)
  line L4 (11.95, 57.3) -> (11.95, 58.65)
  point P2 (11.95, 57.3)
  point P3 (30.05, 57.3)
  point P4 (30.05, 58.65)
  dimension "d833" distance P2 P3 = 18.1
  dimension "d834" distance P3 P4 = 1.35
extrude "Extrude38" cut sketch "Charger roof clears PCB underside profile" against normal blind 1.56
work_plane "WorkPlane39" AlongDistance -13.8 ExtraOffset 0
sketch "POWER roof clears body and bracket profile" plane through (0, 0, -13.8) normal (0, 0, 1) x axis (1, 0, 0)
  line L1 (46.5, 53.15) -> (35.5, 53.15)
  line L2 (46.5, 58.6) -> (46.5, 53.15)
  line L3 (35.5, 58.6) -> (46.5, 58.6)
  line L4 (35.5, 53.15) -> (35.5, 58.6)
  point P2 (35.5, 53.15)
  point P3 (46.5, 53.15)
  point P4 (46.5, 58.6)
  dimension "d839" distance P2 P3 = 11
  dimension "d840" distance P3 P4 = 5.45
extrude "Extrude39" cut sketch "POWER roof clears body and bracket profile" against normal blind 6.5
work_plane "WorkPlane40" AlongDistance -13.95 ExtraOffset 0
sketch "MODE roof clears broad body profile" plane through (0, 0, -13.95) normal (0, 0, 1) x axis (1, 0, 0)
  line L1 (64.75, 55.29) -> (55.25, 55.29)
  line L2 (64.75, 59.05) -> (64.75, 55.29)
  line L3 (55.25, 59.05) -> (64.75, 59.05)
  line L4 (55.25, 55.29) -> (55.25, 59.05)
  point P2 (55.25, 55.29)
  point P3 (64.75, 55.29)
  point P4 (64.75, 59.05)
  dimension "d845" distance P2 P3 = 9.5
  dimension "d846" distance P3 P4 = 3.76
extrude "Extrude40" cut sketch "MODE roof clears broad body profile" against normal blind 4.1
work_plane "WorkPlane83" AlongDistance -9.48 ExtraOffset 0
sketch "Reset guide upper-wall service recess profile" plane through (0, 0, -9.48) normal (0, 0, 1) x axis (1, 0, 0)
  line L1 (93.115, 57.35) -> (88.515, 57.35)
  line L2 (93.115, 60.15) -> (93.115, 57.35)
  line L3 (88.515, 60.15) -> (93.115, 60.15)
  line L4 (88.515, 57.35) -> (88.515, 60.15)
  point P2 (88.515, 57.35)
  point P3 (93.115, 57.35)
  point P4 (93.115, 60.15)
  dimension "d851" distance P2 P3 = 4.6
  dimension "d852" distance P3 P4 = 2.8
extrude "Extrude83" cut sketch "Reset guide upper-wall service recess profile" against normal blind 5.57
work_plane "WorkPlane41" AlongDistance -9.65 ExtraOffset 0
sketch "Reset guide exterior roof completion profile" plane through (0, 0, -9.65) normal (0, 0, 1) x axis (1, 0, 0)
  line L1 (93.115, 57.3) -> (88.515, 57.3)
  line L2 (93.115, 59.75) -> (93.115, 57.3)
  line L3 (88.515, 59.75) -> (93.115, 59.75)
  line L4 (88.515, 57.3) -> (88.515, 59.75)
  point P2 (88.515, 57.3)
  point P3 (93.115, 57.3)
  point P4 (93.115, 59.75)
  dimension "d857" distance P2 P3 = 4.6
  dimension "d858" distance P3 P4 = 2.45
extrude "Extrude41" new body sketch "Reset guide exterior roof completion profile" against normal blind 5.35 bodies "Reset guide exterior roof completion"
combine "Combine2" bodies "Reset guide exterior roof completion"
work_plane "WorkPlane42" AlongDistance -9.63 ExtraOffset 0
sketch "Reopen reset keyway profile" plane through (0, 0, -9.63) normal (0, 0, 1) x axis (1, 0, 0)
  line L1 (93.415, 54.4) -> (90.615, 54.4)
  line L2 (93.415, 57.6) -> (93.415, 54.4)
  line L3 (90.615, 57.6) -> (93.415, 57.6)
  line L4 (90.615, 54.4) -> (90.615, 57.6)
  point P2 (90.615, 54.4)
  point P3 (93.415, 54.4)
  point P4 (93.415, 57.6)
  dimension "d863" distance P2 P3 = 2.8
  dimension "d864" distance P3 P4 = 3.2
extrude "Extrude42" cut sketch "Reopen reset keyway profile" against normal blind 5.4
work_plane "WorkPlane43" AlongDistance -12.4 ExtraOffset 0
sketch "Remove narrow end contact profile" plane through (0, 0, -12.4) normal (0, 0, 1) x axis (1, 0, 0)
  line L1 (91.26, 36.79) -> (89.24, 36.79)
  line L2 (91.26, 38.21) -> (91.26, 36.79)
  line L3 (89.24, 38.21) -> (91.26, 38.21)
  line L4 (89.24, 36.79) -> (89.24, 38.21)
  point P2 (89.24, 36.79)
  point P3 (91.26, 36.79)
  point P4 (91.26, 38.21)
  dimension "d869" distance P2 P3 = 2.02
  dimension "d870" distance P3 P4 = 1.42
extrude "Extrude43" cut sketch "Remove narrow end contact profile" against normal blind 6
work_plane "WorkPlane44" AlongDistance -12.4 ExtraOffset 0
sketch "Remove narrow end contact profile (1)" plane through (0, 0, -12.4) normal (0, 0, 1) x axis (1, 0, 0)
  line L1 (91.26, 56.64) -> (89.24, 56.64)
  line L2 (91.26, 57.81) -> (91.26, 56.64)
  line L3 (89.24, 57.81) -> (91.26, 57.81)
  line L4 (89.24, 56.64) -> (89.24, 57.81)
  point P2 (89.24, 56.64)
  point P3 (91.26, 56.64)
  point P4 (91.26, 57.81)
  dimension "d875" distance P2 P3 = 2.02
  dimension "d876" distance P3 P4 = 1.17
extrude "Extrude44" cut sketch "Remove narrow end contact profile (1)" against normal blind 6
work_plane "WorkPlane45" AlongDistance -12.4 ExtraOffset 0
sketch "Remove narrow end contact profile (2)" plane through (0, 0, -12.4) normal (0, 0, 1) x axis (1, 0, 0)
  line L1 (106.56, 36.79) -> (104.54, 36.79)
  line L2 (106.56, 38.21) -> (106.56, 36.79)
  line L3 (104.54, 38.21) -> (106.56, 38.21)
  line L4 (104.54, 36.79) -> (104.54, 38.21)
  point P2 (104.54, 36.79)
  point P3 (106.56, 36.79)
  point P4 (106.56, 38.21)
  dimension "d881" distance P2 P3 = 2.02
  dimension "d882" distance P3 P4 = 1.42
extrude "Extrude45" cut sketch "Remove narrow end contact profile (2)" against normal blind 6
work_plane "WorkPlane46" AlongDistance -12.4 ExtraOffset 0
sketch "Remove narrow end contact profile (3)" plane through (0, 0, -12.4) normal (0, 0, 1) x axis (1, 0, 0)
  line L1 (106.56, 56.64) -> (104.54, 56.64)
  line L2 (106.56, 57.81) -> (106.56, 56.64)
  line L3 (104.54, 57.81) -> (106.56, 57.81)
  line L4 (104.54, 56.64) -> (104.54, 57.81)
  point P2 (104.54, 56.64)
  point P3 (106.56, 56.64)
  point P4 (106.56, 57.81)
  dimension "d887" distance P2 P3 = 2.02
  dimension "d888" distance P3 P4 = 1.17
extrude "Extrude46" cut sketch "Remove narrow end contact profile (3)" against normal blind 6
work_plane "WorkPlane47" AlongDistance -12.35 ExtraOffset 0
sketch "Broad XIAO short-end contact profile" plane through (0, 0, -12.35) normal (0, 0, 1) x axis (1, 0, 0)
  line L1 (91.4, 36.7) -> (88.9, 36.7)
  line L2 (91.4, 38.7) -> (91.4, 36.7)
  line L3 (88.9, 38.7) -> (91.4, 38.7)
  line L4 (88.9, 36.7) -> (88.9, 38.7)
  point P2 (88.9, 36.7)
  point P3 (91.4, 36.7)
  point P4 (91.4, 38.7)
  dimension "d893" distance P2 P3 = 2.5
  dimension "d894" distance P3 P4 = 2
extrude "Extrude47" new body sketch "Broad XIAO short-end contact profile" against normal blind 5.9 bodies "Broad XIAO short-end contact"
work_plane "WorkPlane48" AlongDistance -12.35 ExtraOffset 0
sketch "Broad XIAO short-end contact profile (1)" plane through (0, 0, -12.35) normal (0, 0, 1) x axis (1, 0, 0)
  line L1 (106.8, 36.7) -> (104.3, 36.7)
  line L2 (106.8, 38.7) -> (106.8, 36.7)
  line L3 (104.3, 38.7) -> (106.8, 38.7)
  line L4 (104.3, 36.7) -> (104.3, 38.7)
  point P2 (104.3, 36.7)
  point P3 (106.8, 36.7)
  point P4 (106.8, 38.7)
  dimension "d899" distance P2 P3 = 2.5
  dimension "d900" distance P3 P4 = 2
extrude "Extrude48" new body sketch "Broad XIAO short-end contact profile (1)" against normal blind 5.9 bodies "Broad XIAO short-end contact (1)"
work_plane "WorkPlane49" AlongDistance -12.35 ExtraOffset 0
sketch "Broad XIAO short-end contact profile (2)" plane through (0, 0, -12.35) normal (0, 0, 1) x axis (1, 0, 0)
  line L1 (90.8, 55.8) -> (88.4, 55.8)
  line L2 (90.8, 58.2) -> (90.8, 55.8)
  line L3 (88.4, 58.2) -> (90.8, 58.2)
  line L4 (88.4, 55.8) -> (88.4, 58.2)
  point P2 (88.4, 55.8)
  point P3 (90.8, 55.8)
  point P4 (90.8, 58.2)
  dimension "d905" distance P2 P3 = 2.4
  dimension "d906" distance P3 P4 = 2.4
extrude "Extrude49" new body sketch "Broad XIAO short-end contact profile (2)" against normal blind 5.9 bodies "Broad XIAO short-end contact (2)"
work_plane "WorkPlane50" AlongDistance -12.35 ExtraOffset 0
